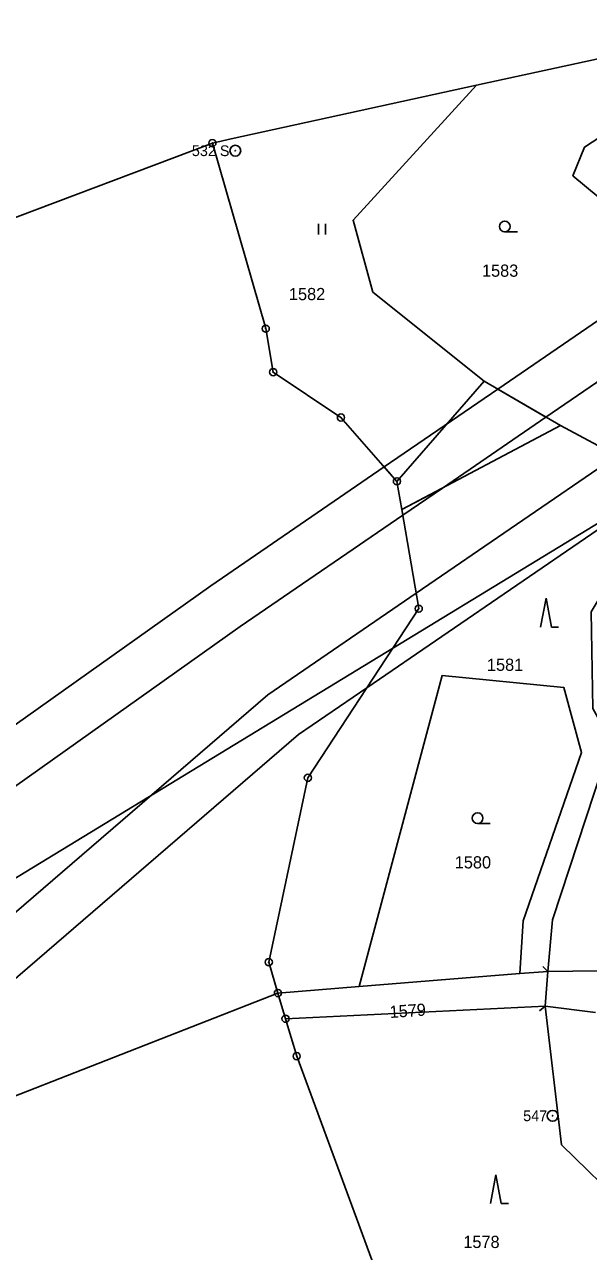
# Model space of a CAD drawing. Extents: x -504988 to -494607, y -1123820 to -1114018.
# Drawn here: x -498857.1 to -498778.6, y -1118382.3 to -1118211.4 of the extents above; entities that cross this region are included whole.
import ezdxf

# ---------------------------------------------------------------- set-up
doc = ezdxf.new("R2010")
doc.units = 0
for name, color, linetype in [('Hranice parcel', 7, 'Continuous'), ('Parcelní čísla', 7, 'Continuous'), ('Poz předměty', 7, 'Continuous'), ('Vnitřní kresba', 7, 'Continuous'), ('Věcná břemena k části', 7, 'Continuous'), ('Značky bodu BP', 7, 'Continuous'), ('Značky kultur', 7, 'Continuous')]:
    doc.layers.add(name, color=color, linetype=linetype)

msp = doc.modelspace()

# ---------------------------------------------------------------- linework, layer by layer
at = {"layer": 'Hranice parcel'}
for p, q in [((-498755.45, -1118211.41), (-498794.15, -1118219.87)), ((-498794.15, -1118219.87), (-498828.31, -1118227.34)), ((-498874.35, -1118244.3), (-498830.94, -1118227.92)), ((-498828.31, -1118227.34), (-498830.94, -1118227.92)), ((-498782.47, -1118267.25), (-498804.56, -1118278.96)), ((-498767.41, -1118275.32), (-498782.47, -1118267.25)), ((-498788.12, -1118343.54), (-498810.51, -1118345.36)), ((-498788.12, -1118343.54), (-498784.21, -1118343.29)), ((-498784.21, -1118343.29), (-498784.59, -1118348.11)), ((-498821.81, -1118346.28), (-498981.16, -1118408.67)), ((-498821.81, -1118346.28), (-498810.51, -1118345.36)), ((-498820.75, -1118349.85), (-498821.81, -1118346.28)), ((-498784.59, -1118348.11), (-498820.75, -1118349.85))]:
    msp.add_line(p, q, dxfattribs=at)
for points in [[(-498755.45, -1118211.41), (-498764.66, -1118219.08), (-498779.1, -1118228.47), (-498780.72, -1118232.46), (-498773.68, -1118238.31), (-498770.81, -1118242.41), (-498763.98, -1118258.5), (-498764.84, -1118264.89), (-498767.53, -1118273.38), (-498767.41, -1118275.32)], [(-498782.47, -1118267.25), (-498793.1, -1118261.09), (-498808.57, -1118248.67), (-498811.35, -1118238.67), (-498794.15, -1118219.87)], [(-498830.94, -1118227.92), (-498823.51, -1118253.76), (-498822.48, -1118259.81), (-498813.03, -1118266.13), (-498805.23, -1118275.02), (-498804.56, -1118278.96)], [(-498784.21, -1118343.29), (-498783.58, -1118336.09), (-498775.38, -1118311.27), (-498777.94, -1118306.66), (-498778.18, -1118293.18), (-498767.41, -1118275.32)], [(-498804.56, -1118278.96), (-498802.2, -1118292.75), (-498817.64, -1118316.3), (-498823.09, -1118341.98), (-498821.81, -1118346.28)], [(-498810.51, -1118345.36), (-498798.92, -1118302.05), (-498781.99, -1118303.71), (-498779.52, -1118312.76), (-498787.65, -1118336.2), (-498788.12, -1118343.54)], [(-498784.59, -1118348.11), (-498782.3, -1118367.4), (-498773.18, -1118376.34), (-498762.56, -1118388.15)], [(-498801.74, -1118402.47), (-498819.2, -1118355.06), (-498820.75, -1118349.85)]]:
    msp.add_lwpolyline(points, dxfattribs=at)
at = {"layer": 'Poz předměty'}
msp.add_line((-498881.92, -1118344.6), (-498709.94, -1118239.91), dxfattribs=at)
at = {"layer": 'Vnitřní kresba'}
for p, q in [((-498793.1, -1118261.09), (-498805.23, -1118275.02)), ((-498784.93, -1118342.59), (-498784.21, -1118343.29)), ((-498777.27, -1118343.2), (-498784.21, -1118343.29)), ((-498785.38, -1118348.73), (-498784.59, -1118348.11)), ((-498777.59, -1118348.98), (-498784.59, -1118348.11))]:
    msp.add_line(p, q, dxfattribs=at)
at = {"layer": 'Věcná břemena k části'}
for points in [[(-498766.1, -1118253.5), (-498768.89, -1118246.93), (-498791.19, -1118262.2), (-498784.48, -1118266.09)], [(-498806.99, -1118273.01), (-498805.23, -1118275.02), (-498804.56, -1118278.96), (-498798.9, -1118275.96), (-498784.48, -1118266.09), (-498791.19, -1118262.2)], [(-498804.43, -1118279.74), (-498798.9, -1118275.96), (-498804.56, -1118278.96), (-498805.23, -1118275.02), (-498806.99, -1118273.01), (-498831.16, -1118289.56), (-498995.39, -1118406.16), (-498991.36, -1118411.89), (-498827.06, -1118295.24)], [(-498767.66, -1118275.19), (-498774.61, -1118271.46), (-498802.57, -1118290.6), (-498823.23, -1118304.74), (-498912.77, -1118381.9), (-498893.13, -1118374.2), (-498818.96, -1118310.29), (-498809.42, -1118303.76)]]:
    msp.add_lwpolyline(points, close=True, dxfattribs=at)
at = {"layer": 'Značky bodu BP'}
for centre, radius in [((-498830.94, -1118227.92), 0.5), ((-498830.94, -1118227.92), 0.0303), ((-498827.75, -1118228.98), 0.75), ((-498827.75, -1118228.98), 0.03), ((-498823.51, -1118253.76), 0.5), ((-498823.51, -1118253.76), 0.0303), ((-498822.48, -1118259.81), 0.5), ((-498822.48, -1118259.81), 0.0303), ((-498813.03, -1118266.13), 0.5), ((-498813.03, -1118266.13), 0.0303), ((-498805.23, -1118275.02), 0.5), ((-498805.23, -1118275.02), 0.0303), ((-498802.2, -1118292.75), 0.5), ((-498802.2, -1118292.75), 0.0303), ((-498817.64, -1118316.3), 0.5), ((-498817.64, -1118316.3), 0.0303), ((-498823.09, -1118341.98), 0.5), ((-498823.09, -1118341.98), 0.0303), ((-498821.81, -1118346.28), 0.5), ((-498821.81, -1118346.28), 0.0303), ((-498820.75, -1118349.85), 0.5), ((-498820.75, -1118349.85), 0.0303), ((-498819.2, -1118355.06), 0.5), ((-498819.2, -1118355.06), 0.0303), ((-498783.55, -1118363.37), 0.75), ((-498783.55, -1118363.37), 0.03)]:
    msp.add_circle(centre, radius, dxfattribs=at)
at = {"layer": 'Značky kultur'}
for p, q in [((-498816.18, -1118240.65), (-498816.18, -1118239.15)), ((-498815.18, -1118240.65), (-498815.18, -1118239.15)), ((-498790.21, -1118240.28), (-498788.46, -1118240.28)), ((-498784.47, -1118291.31), (-498785.22, -1118295.31)), ((-498783.72, -1118295.31), (-498784.47, -1118291.31)), ((-498783.72, -1118295.31), (-498782.72, -1118295.31)), ((-498794, -1118322.67), (-498792.25, -1118322.67)), ((-498791.46, -1118371.57), (-498792.21, -1118375.57)), ((-498790.71, -1118375.57), (-498791.46, -1118371.57)), ((-498790.71, -1118375.57), (-498789.71, -1118375.57))]:
    msp.add_line(p, q, dxfattribs=at)
for centre in [(-498790.21, -1118239.53), (-498794, -1118321.92)]:
    msp.add_circle(centre, 0.75, dxfattribs=at)

# ---------------------------------------------------------------- texts
at = {"layer": 'Parcelní čísla'}
for s, p in [('1583', (-498793.39, -1118246.53)), ('1582', (-498820.28, -1118249.79)), ('1581', (-498792.7, -1118301.41)), ('1580', (-498797.18, -1118328.92)), ('1578', (-498795.99, -1118381.78))]:
    msp.add_text(s, height=1.7, dxfattribs=at).set_placement(p)
msp.add_text('1579', height=1.7, rotation=4, dxfattribs=at).set_placement((-498806.2, -1118349.76))
at = {"layer": 'Značky bodu BP'}
for s, p in [('532 S', (-498833.8, -1118229.73)), ('547', (-498787.65, -1118364.12))]:
    msp.add_text(s, height=1.5, dxfattribs=at).set_placement(p)

doc.saveas('drawing.dxf')
